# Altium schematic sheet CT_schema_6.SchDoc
size 147 x 119 mm
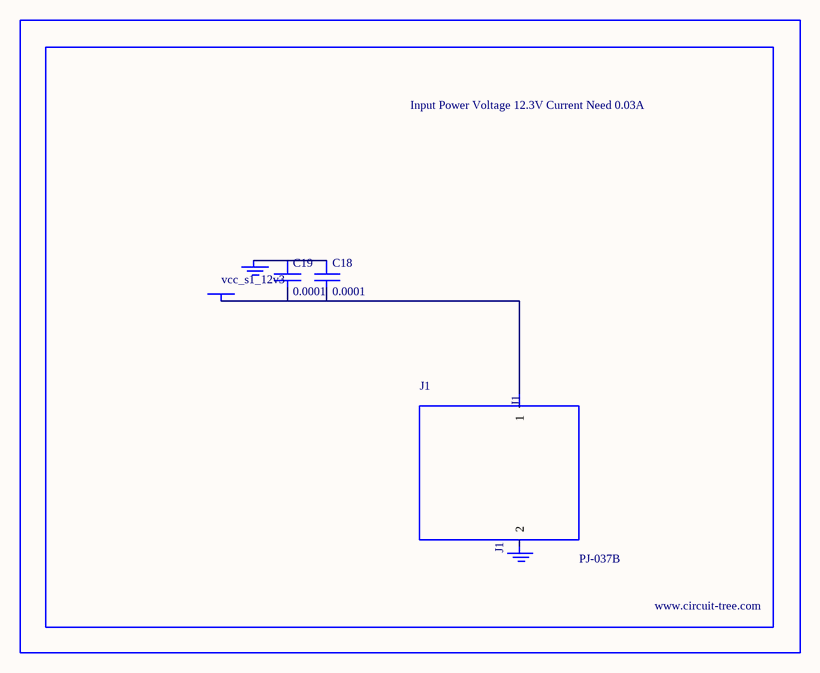
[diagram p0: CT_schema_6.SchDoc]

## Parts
BORDER5  (no value)
C18  0.0001  [EXV-9H]
C19  0.0001  [EXV-9H]
GND_INSTANCE_5_0  (no value)
GND_INSTANCE_5_1  (no value)
J1  PJ-037B  [PJ-037B_PACKAGE]
POWER_INSTANCE_5_0  vcc_s1_12v3

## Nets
NetC18_1: C18.1 C19.1 GND_INSTANCE_5_0.0(GND)
NetC18_2: C18.2 C19.2 J1.1 POWER_INSTANCE_5_0.0(PWR)

Not connected (* = marked no-connect by the designer): GND_INSTANCE_5_1 0(GND); J1 2

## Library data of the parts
BORDER5 = BORDER_PAGE5
C18 C19 = EDK107M035A9HAA
GND_INSTANCE_5_0 GND_INSTANCE_5_1 = GND
POWER_INSTANCE_5_0 = PWR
